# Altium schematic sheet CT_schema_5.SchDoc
size 383 x 311 mm
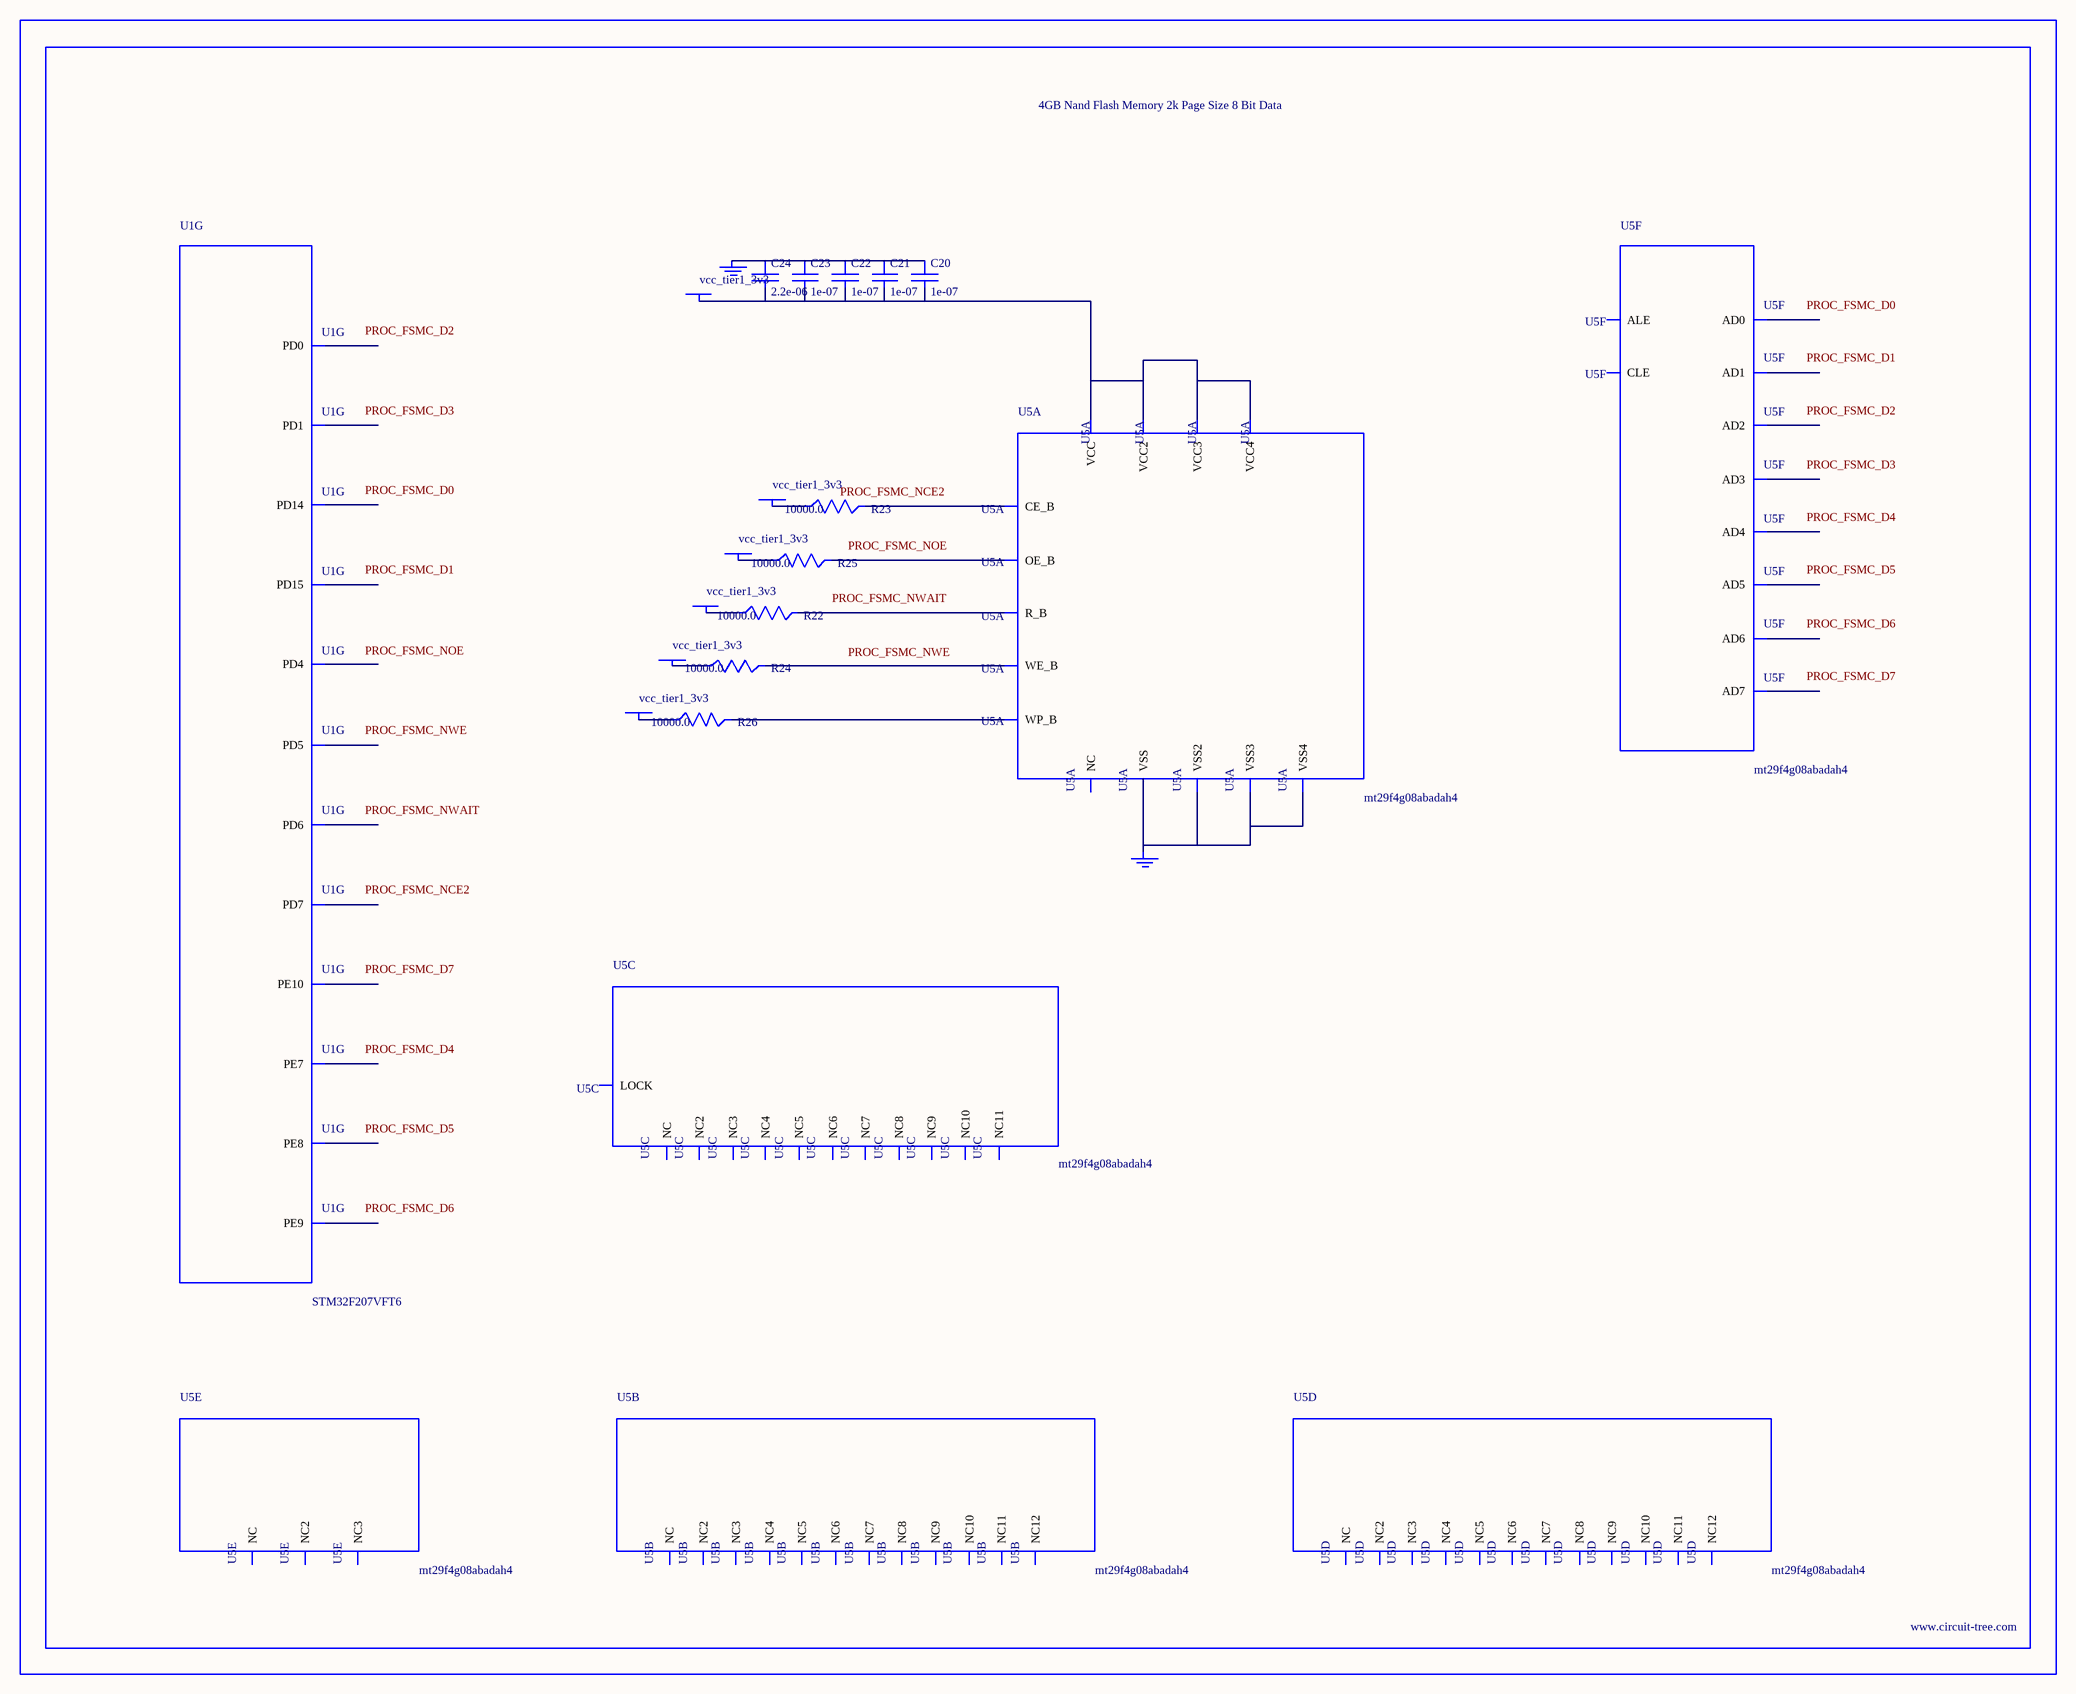
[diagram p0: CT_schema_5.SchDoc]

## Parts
BORDER4  (no value)
C20  1e-07  [C0402]
C21  1e-07  [C0402]
C22  1e-07  [C0402]
C23  1e-07  [C0402]
C24  2.2e-06  [C0603]
GND_INSTANCE_4_0  (no value)
GND_INSTANCE_4_1  (no value)
POWER_INSTANCE_4_0  vcc_tier1_3v3
POWER_INSTANCE_4_1  vcc_tier1_3v3
POWER_INSTANCE_4_2  vcc_tier1_3v3
POWER_INSTANCE_4_3  vcc_tier1_3v3
POWER_INSTANCE_4_4  vcc_tier1_3v3
POWER_INSTANCE_4_5  vcc_tier1_3v3
R22  10000.0  [R0603]
R23  10000.0  [R0603]
R24  10000.0  [R0603]
R25  10000.0  [R0603]
R26  10000.0  [R0603]
U1  STM32F207VFT6  [LQFP100]  (part G of 7)
U5  mt29f4g08abadah4  [VFBGA-63]  (parts A,B,C,D,E,F of 6)

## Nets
NetC20_1: C20.1 C21.1 C22.1 C23.1 C24.1 GND_INSTANCE_4_0.0(GND)
NetC20_2: C20.2 C21.2 C22.2 C23.2 C24.2 POWER_INSTANCE_4_0.0(PWR) U5.D3(VCC) U5.G4(VCC2) U5.H8(VCC3) U5.J6(VCC4)
NetGND_INSTANCE_4_1_0: GND_INSTANCE_4_1.0(GND) U5.C5(VSS) U5.F7(VSS2) U5.K3(VSS3) U5.K8(VSS4)
NetPOWER_INSTANCE_4_1_0: POWER_INSTANCE_4_1.0(PWR) R22.1
NetPOWER_INSTANCE_4_2_0: POWER_INSTANCE_4_2.0(PWR) R23.1
NetPOWER_INSTANCE_4_3_0: POWER_INSTANCE_4_3.0(PWR) R24.1
NetPOWER_INSTANCE_4_4_0: POWER_INSTANCE_4_4.0(PWR) R25.1
NetPOWER_INSTANCE_4_5_0: POWER_INSTANCE_4_5.0(PWR) R26.1
NetR22_2: R22.2 U5.C8(R_B)
NetR23_2: R23.2 U5.C6(CE_B)
NetR24_2: R24.2 U5.C7(WE_B)
NetR25_2: R25.2 U5.D4(OE_B)
NetR26_2: R26.2 U5.C3(WP_B)

Not connected (* = marked no-connect by the designer): U1 38(PE7) 39(PE8) 40(PE9) 41(PE10) 61(PD14) 62(PD15) 81(PD0) 82(PD1) 85(PD4) 86(PD5) 87(PD6) 88(PD7); U5 A1(NC) A2(NC3) A9(NC4) A10(NC2) B1(NC5) B9(NC7) B10(NC6) C4(ALE) D5(CLE) D6(NC8) D7(NC9) D8(NC10) E3(NC11) E4(NC12) E5(NC) E6(NC2) E7(NC3) E8(NC4) F3(NC5) F4(NC6) F5(NC7) F6(NC8) F8(NC9) G3(NC) G5(LOCK) G6(NC10) G7(NC11) G8(NC) H3(NC2) H4(AD0) H5(NC3) H6(NC4) H7(NC5) J3(NC6) J4(AD1) J5(NC7) J7(AD5) J8(AD7) K4(AD2) K5(AD3) K6(AD4) K7(AD6) L1(NC8) L2(NC10) L9(NC11) L10(NC9) M1(NC12) M2(NC2) M9(NC3) M10(NC)

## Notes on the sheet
- Labels drawn without touching a wire or pin: PROC_FSMC_D0, PROC_FSMC_D1, PROC_FSMC_D2, PROC_FSMC_D3, PROC_FSMC_D4, PROC_FSMC_D5, PROC_FSMC_D6, PROC_FSMC_D7, PROC_FSMC_NCE2, PROC_FSMC_NOE, PROC_FSMC_NWAIT, PROC_FSMC_NWE

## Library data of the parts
BORDER4 = BORDER_PAGE4
C20-C23 = C0402C104K3RACTU
C24 = C0603C225K8RACTU
GND_INSTANCE_4_0 GND_INSTANCE_4_1 = GND
POWER_INSTANCE_4_0-POWER_INSTANCE_4_5 = PWR
R22-R26 = RC0603JR-0710KL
